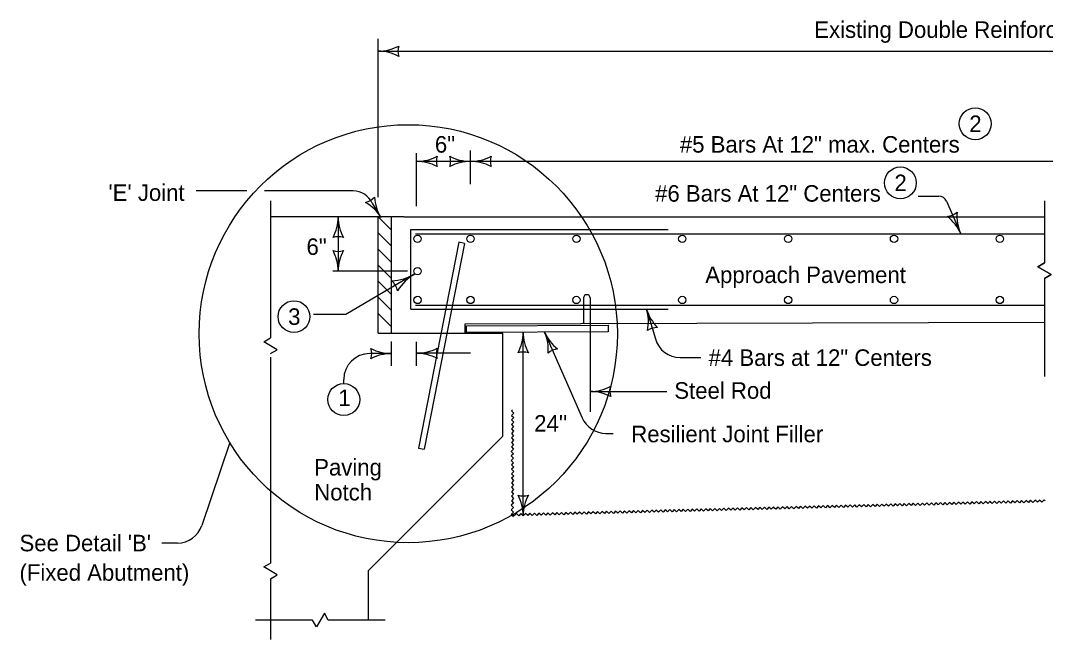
# Model space of a CAD drawing. Extents: x -2134860 to -2124557, y -2139046 to -2137324.
# Drawn here: x -2134860 to -2133869, y -2137923 to -2137324 of the extents above; entities that cross this region are included whole.
import ezdxf

# ---------------------------------------------------------------- set-up
doc = ezdxf.new("R2010")
doc.units = 0
for name, color, linetype in [('BridgeSuperStructureExisting', 7, 'Continuous'), ('dsnCellElements', 7, 'Continuous'), ('dsnStdLabel', 7, 'Continuous'), ('dsnTextFinalPlan', 7, 'Continuous')]:
    doc.layers.add(name, color=color, linetype=linetype)

msp = doc.modelspace()

# ---------------------------------------------------------------- linework, layer by layer
at = {"layer": 'BridgeSuperStructureExisting'}
for p, q in [((-2134618.16, -2137498.29), (-2134618.16, -2137537.43)), ((-2134519.9, -2137500.82), (-2134511.57, -2137514.44)), ((-2133870.3, -2137498.29), (-2133870.3, -2137558.37)), ((-2134489.26, -2137513.92), (-2134618.16, -2137513.92)), ((-2134514.26, -2137626.46), (-2134514.26, -2137513.92)), ((-2134501.39, -2137526.79), (-2134514.26, -2137513.92)), ((-2134489.26, -2137513.92), (-2133870.3, -2137513.92)), ((-2134482.68, -2137526.02), (-2134233.83, -2137526.02)), ((-2134482.68, -2137603.18), (-2134482.68, -2137526.02)), ((-2134501.39, -2137542.35), (-2134514.26, -2137529.48)), ((-2134478.05, -2137530.22), (-2133870.3, -2137530.22)), ((-2134618.16, -2137537.43), (-2134618.16, -2137631.03)), ((-2134501.39, -2137557.91), (-2134514.26, -2137545.04)), ((-2134501.39, -2137573.46), (-2134514.26, -2137560.59)), ((-2134501.39, -2137589.02), (-2134514.26, -2137576.15)), ((-2133870.3, -2137573.53), (-2133870.3, -2137668.14)), ((-2134501.39, -2137604.58), (-2134514.26, -2137591.71)), ((-2134482.68, -2137603.18), (-2134233.83, -2137603.18)), ((-2134478.05, -2137599.18), (-2133870.3, -2137599.18)), ((-2134501.39, -2137620.13), (-2134514.26, -2137607.26)), ((-2133870.3, -2137616.23), (-2134430.47, -2137617.72)), ((-2134428.74, -2137619.18), (-2134291.82, -2137618.68)), ((-2134428.72, -2137625.66), (-2134428.74, -2137619.18)), ((-2134291.8, -2137625.16), (-2134428.72, -2137625.66)), ((-2134291.82, -2137618.68), (-2134291.8, -2137625.16)), ((-2134514.26, -2137626.46), (-2134393.54, -2137626.46)), ((-2134393.53, -2137726.07), (-2134393.53, -2137626.46)), ((-2134618.16, -2137649.56), (-2134618.16, -2137848.65)), ((-2134523.37, -2137855.9), (-2134393.53, -2137726.07)), ((-2134618.16, -2137863.81), (-2134618.16, -2137922.62)), ((-2134523.37, -2137903.76), (-2134523.37, -2137855.9)), ((-2134577.54, -2137903.76), (-2134632.6, -2137903.76)), ((-2134507.32, -2137903.76), (-2134562.38, -2137903.76))]:
    msp.add_line(p, q, dxfattribs=at)
for points in [[(-2133870.3, -2137573.53), (-2133863.73, -2137569.74), (-2133876.86, -2137562.15), (-2133870.3, -2137558.37)], [(-2134618.15, -2137646.19), (-2134611.59, -2137642.41), (-2134624.72, -2137634.82), (-2134618.15, -2137631.04)], [(-2134618.15, -2137863.82), (-2134611.59, -2137860.03), (-2134624.72, -2137852.44), (-2134618.15, -2137848.66)], [(-2134562.37, -2137903.76), (-2134566.16, -2137897.2), (-2134573.75, -2137910.33), (-2134577.54, -2137903.76)]]:
    msp.add_lwpolyline(points, dxfattribs=at)
for centre, radius in [((-2133937.23, -2137423.93), 15.36), ((-2134009.56, -2137481.05), 15.36), ((-2134476.05, -2137535.22), 3.55), ((-2134424.9, -2137535.22), 3.55), ((-2134322.6, -2137535.22), 3.55), ((-2134220.29, -2137535.22), 3.55), ((-2134117.99, -2137535.22), 3.55), ((-2134015.68, -2137535.22), 3.55), ((-2133913.38, -2137535.22), 3.55), ((-2134595.54, -2137610.4), 15.36), ((-2134476.05, -2137594.28), 3.55), ((-2134424.9, -2137594.28), 3.55), ((-2134322.6, -2137594.28), 3.55), ((-2134220.29, -2137594.28), 3.55), ((-2134117.99, -2137594.28), 3.55), ((-2134015.68, -2137594.28), 3.55), ((-2133913.38, -2137594.28), 3.55), ((-2134547.36, -2137690.56), 15.36)]:
    msp.add_circle(centre, radius, dxfattribs=at)
for centre, radius, start, end in [((-2133965.92, -2137496.71), 16.85, 275.90677, 311.37347), ((-2133991.22, -2137547.72), 43.63, 23.64012, 51.71261), ((-2133911.28, -2137512.73), 43.63, 175.56763, 203.64012), ((-2134503.18, -2137527.36), 48.39, 272.40408, 300.47657), ((-2134513.6, -2137589.64), 18.69, 12.74322, 48.20992), ((-2134454.1, -2137610.76), 48.39, 120.47657, 148.54906), ((-2134222.28, -2137624.99), 25, 196.32643, 270), ((-2134522.36, -2137671.15), 25, 90, 180), ((-2134294.12, -2137698.28), 25, 203.64012, 270), ((-2134373.99, -2137767.33), 16.42, 252.26665, 287.73335), ((-2134416.49, -2137802.97), 42.5, 360, 28.07249), ((-2134331.49, -2137802.97), 42.5, 151.92751, 180), ((-2134708.21, -2137804.34), 25, 270, 341.40579)]:
    msp.add_arc(centre, radius, start, end, dxfattribs=at)
at = {"layer": 'dsnCellElements'}
for centre, radius, start, end in [((-2134514.26, -2137311.22), 42.5, 270, 298.07249), ((-2134478.62, -2137353.72), 16.42, 162.26665, 197.73335), ((-2134514.26, -2137396.22), 42.5, 61.92751, 90), ((-2134477.12, -2137417.78), 42.5, 270, 298.07249), ((-2134441.49, -2137460.28), 16.42, 162.26665, 197.73335), ((-2134460.54, -2137460.28), 16.42, 342.26665, 17.73335), ((-2134424.9, -2137417.78), 42.5, 241.92751, 270), ((-2134424.9, -2137417.78), 42.5, 270, 298.07249), ((-2134389.27, -2137460.28), 16.42, 162.26665, 197.73335), ((-2134477.12, -2137502.78), 42.5, 61.92751, 90), ((-2134424.9, -2137502.78), 42.5, 90, 118.07249), ((-2134424.9, -2137502.78), 42.5, 61.92751, 90), ((-2134530.16, -2137484.04), 16.42, 283.71154, 319.17824), ((-2134475.31, -2137492.27), 42.5, 183.3724, 211.44489), ((-2134547.83, -2137536.62), 42.5, 31.44489, 59.51738), ((-2134595.26, -2137513.92), 42.5, 331.92751, 360), ((-2134510.26, -2137513.92), 42.5, 180, 208.07249), ((-2134552.76, -2137549.56), 16.42, 72.26665, 107.73335), ((-2134552.76, -2137530.95), 16.42, 252.26665, 287.73335), ((-2134595.26, -2137566.59), 42.5, 360, 28.07249), ((-2134510.26, -2137566.59), 42.5, 151.92751, 180), ((-2134213.93, -2137591.24), 42.5, 196.32643, 224.39892), ((-2134295.5, -2137615.13), 42.5, 348.25394, 16.32643), ((-2134416.49, -2137625.46), 42.5, 331.92751, 360), ((-2134331.49, -2137625.46), 42.5, 180, 208.07249), ((-2134314.38, -2137608.34), 42.5, 203.64012, 231.71261), ((-2134392.25, -2137642.43), 42.5, 355.56763, 23.64012), ((-2134244.7, -2137637.38), 16.42, 88.59307, 124.05978), ((-2134536.83, -2137646.15), 16.42, 342.26665, 17.73335), ((-2134501.19, -2137603.65), 42.5, 241.92751, 270), ((-2134477.12, -2137603.37), 42.5, 270, 298.07249), ((-2134477.12, -2137688.37), 42.5, 61.92751, 90), ((-2134441.49, -2137645.87), 16.42, 162.26665, 197.73335), ((-2134373.99, -2137661.1), 16.42, 72.26665, 107.73335), ((-2134339.03, -2137658.03), 16.42, 95.90677, 131.37347), ((-2134501.19, -2137688.65), 42.5, 90, 118.07249), ((-2134309.44, -2137640.24), 42.5, 270, 298.07249), ((-2134309.44, -2137725.24), 42.5, 61.92751, 90), ((-2134273.81, -2137682.74), 16.42, 162.26665, 197.73335)]:
    msp.add_arc(centre, radius, start, end, dxfattribs=at)
at = {"layer": 'dsnStdLabel'}
for p, q in [((-2134514.26, -2137460.6), (-2134514.26, -2137341.67)), ((-2134514.26, -2137353.72), (-2133142.62, -2137353.72)), ((-2134477.12, -2137503.61), (-2134477.12, -2137452.42)), ((-2134424.9, -2137482.26), (-2134424.9, -2137449.69)), ((-2134514.26, -2137494.97), (-2134514.26, -2137460.6)), ((-2134424.9, -2137460.28), (-2134477.12, -2137460.28)), ((-2133854.65, -2137460.28), (-2134424.9, -2137460.28)), ((-2134681.13, -2137488.71), (-2134690, -2137488.71)), ((-2134641.15, -2137488.71), (-2134681.13, -2137488.71)), ((-2134538.42, -2137488.71), (-2134623.84, -2137488.71)), ((-2133992.31, -2137493.87), (-2133972.45, -2137493.87)), ((-2133965.05, -2137498.71), (-2133951.25, -2137530.22)), ((-2134552.76, -2137513.92), (-2134552.76, -2137566.59)), ((-2134501.39, -2137626.46), (-2134501.39, -2137513.92)), ((-2134436.23, -2137538.53), (-2134475.25, -2137737.56)), ((-2134430.67, -2137539.62), (-2134469.7, -2137738.65)), ((-2134430.67, -2137539.62), (-2134436.23, -2137538.53)), ((-2134485.85, -2137566.59), (-2134557.96, -2137566.59)), ((-2133870.3, -2137558.37), (-2133876.86, -2137562.15)), ((-2133876.86, -2137562.15), (-2133863.73, -2137569.74)), ((-2134478.64, -2137569.06), (-2134545.54, -2137608.43)), ((-2133863.73, -2137569.74), (-2133870.3, -2137573.53)), ((-2134254.72, -2137603.18), (-2134246.27, -2137632.01)), ((-2134545.54, -2137608.43), (-2134576.73, -2137608.43)), ((-2134430.47, -2137617.72), (-2134430.47, -2137626.46)), ((-2134428.74, -2137619.18), (-2134291.82, -2137618.68)), ((-2134428.72, -2137625.66), (-2134428.74, -2137619.18)), ((-2134291.8, -2137625.16), (-2134428.72, -2137625.66)), ((-2134373.99, -2137802.97), (-2134373.99, -2137625.46)), ((-2134353.32, -2137625.39), (-2134317.02, -2137708.31)), ((-2134291.82, -2137618.68), (-2134291.8, -2137625.16)), ((-2134501.39, -2137657.87), (-2134501.39, -2137634.56)), ((-2134477.12, -2137658.02), (-2134477.12, -2137634.7)), ((-2134424.9, -2137645.87), (-2134477.12, -2137645.87)), ((-2134501.19, -2137646.15), (-2134522.36, -2137646.15)), ((-2134222.28, -2137649.99), (-2134202.5, -2137649.99)), ((-2134547.36, -2137675.2), (-2134547.36, -2137671.15)), ((-2134309.44, -2137682.74), (-2134235.11, -2137682.74)), ((-2134294.12, -2137723.28), (-2134286.92, -2137723.28)), ((-2134657.57, -2137732.22), (-2134684.51, -2137812.31)), ((-2134475.25, -2137737.56), (-2134469.7, -2137738.65)), ((-2134708.21, -2137829.34), (-2134723.21, -2137829.34))]:
    msp.add_line(p, q, dxfattribs=at)
for points in [[(-2134384.26, -2137700.47), (-2134385.35, -2137701.55), (-2134383.18, -2137703.74), (-2134385.37, -2137705.91), (-2134383.2, -2137708.1), (-2134385.38, -2137710.27), (-2134383.21, -2137712.46), (-2134385.4, -2137714.63), (-2134383.22, -2137716.82), (-2134385.41, -2137719), (-2134383.24, -2137721.18), (-2134385.42, -2137723.35), (-2134383.26, -2137725.54), (-2134385.44, -2137727.71), (-2134383.27, -2137729.9), (-2134385.46, -2137732.08), (-2134383.28, -2137734.26), (-2134385.47, -2137736.44), (-2134383.3, -2137738.62), (-2134385.48, -2137740.8), (-2134383.31, -2137742.98), (-2134385.5, -2137745.16), (-2134383.33, -2137747.35), (-2134385.51, -2137749.52), (-2134383.34, -2137751.7), (-2134384.44, -2137752.78)], [(-2134384.26, -2137752.53), (-2134385.35, -2137753.62), (-2134383.19, -2137755.81), (-2134385.37, -2137757.98), (-2134383.2, -2137760.17), (-2134385.38, -2137762.34), (-2134383.21, -2137764.53), (-2134385.4, -2137766.7), (-2134383.23, -2137768.89), (-2134385.41, -2137771.07), (-2134383.24, -2137773.25), (-2134385.42, -2137775.42), (-2134383.26, -2137777.61), (-2134385.44, -2137779.78), (-2134383.27, -2137781.97), (-2134385.46, -2137784.15), (-2134383.28, -2137786.33), (-2134385.47, -2137788.51), (-2134383.3, -2137790.69), (-2134385.49, -2137792.87), (-2134383.31, -2137795.05), (-2134385.5, -2137797.22), (-2134383.33, -2137799.41), (-2134385.51, -2137801.58), (-2134383.34, -2137803.77)], [(-2134131.04, -2137795.5), (-2134132.16, -2137794.45), (-2134134.29, -2137796.68), (-2134136.52, -2137794.56), (-2134138.64, -2137796.79), (-2134140.88, -2137794.67), (-2134143, -2137796.9), (-2134145.24, -2137794.78), (-2134147.36, -2137797.02), (-2134149.6, -2137794.9), (-2134151.72, -2137797.13), (-2134153.95, -2137795.01), (-2134156.08, -2137797.24), (-2134158.32, -2137795.12), (-2134160.44, -2137797.36), (-2134162.67, -2137795.24), (-2134164.8, -2137797.47), (-2134167.03, -2137795.35), (-2134169.16, -2137797.59), (-2134171.4, -2137795.47), (-2134173.51, -2137797.7), (-2134175.75, -2137795.58), (-2134177.87, -2137797.82), (-2134180.11, -2137795.69), (-2134182.23, -2137797.93), (-2134183.35, -2137796.87)], [(-2134078.74, -2137794.13), (-2134079.85, -2137793.08), (-2134081.98, -2137795.31), (-2134084.22, -2137793.19), (-2134086.34, -2137795.42), (-2134088.57, -2137793.31), (-2134090.7, -2137795.54), (-2134092.93, -2137793.42), (-2134095.06, -2137795.65), (-2134097.29, -2137793.53), (-2134099.41, -2137795.76), (-2134101.65, -2137793.64), (-2134103.77, -2137795.88), (-2134106.01, -2137793.76), (-2134108.13, -2137795.99), (-2134110.37, -2137793.87), (-2134112.49, -2137796.11), (-2134114.73, -2137793.98), (-2134116.85, -2137796.22), (-2134119.09, -2137794.1), (-2134121.21, -2137796.34), (-2134123.45, -2137794.22), (-2134125.57, -2137796.45), (-2134127.8, -2137794.33), (-2134129.92, -2137796.56), (-2134131.04, -2137795.5)], [(-2134026.43, -2137792.77), (-2134027.55, -2137791.71), (-2134029.67, -2137793.94), (-2134031.91, -2137791.83), (-2134034.03, -2137794.06), (-2134036.27, -2137791.94), (-2134038.39, -2137794.17), (-2134040.63, -2137792.05), (-2134042.75, -2137794.28), (-2134044.99, -2137792.17), (-2134047.11, -2137794.4), (-2134049.35, -2137792.28), (-2134051.46, -2137794.51), (-2134053.7, -2137792.39), (-2134055.82, -2137794.63), (-2134058.06, -2137792.5), (-2134060.18, -2137794.74), (-2134062.42, -2137792.62), (-2134064.55, -2137794.85), (-2134066.78, -2137792.73), (-2134068.9, -2137794.97), (-2134071.14, -2137792.85), (-2134073.26, -2137795.08), (-2134075.5, -2137792.96), (-2134077.62, -2137795.2), (-2134078.74, -2137794.13)], [(-2133974.12, -2137791.4), (-2133975.24, -2137790.35), (-2133977.36, -2137792.58), (-2133979.6, -2137790.46), (-2133981.72, -2137792.69), (-2133983.96, -2137790.57), (-2133986.09, -2137792.81), (-2133988.32, -2137790.69), (-2133990.44, -2137792.92), (-2133992.68, -2137790.8), (-2133994.8, -2137793.03), (-2133997.04, -2137790.91), (-2133999.16, -2137793.14), (-2134001.4, -2137791.03), (-2134003.52, -2137793.26), (-2134005.76, -2137791.14), (-2134007.87, -2137793.37), (-2134010.11, -2137791.25), (-2134012.24, -2137793.49), (-2134014.47, -2137791.37), (-2134016.6, -2137793.6), (-2134018.83, -2137791.48), (-2134020.96, -2137793.72), (-2134023.19, -2137791.6), (-2134025.31, -2137793.83), (-2134026.43, -2137792.77)], [(-2133921.81, -2137790.04), (-2133922.93, -2137788.98), (-2133925.06, -2137791.21), (-2133927.29, -2137789.09), (-2133929.42, -2137791.32), (-2133931.65, -2137789.21), (-2133933.78, -2137791.44), (-2133936.02, -2137789.32), (-2133938.14, -2137791.55), (-2133940.37, -2137789.43), (-2133942.5, -2137791.66), (-2133944.73, -2137789.55), (-2133946.85, -2137791.78), (-2133949.09, -2137789.66), (-2133951.21, -2137791.89), (-2133953.45, -2137789.77), (-2133955.57, -2137792), (-2133957.8, -2137789.89), (-2133959.93, -2137792.12), (-2133962.17, -2137790), (-2133964.29, -2137792.23), (-2133966.52, -2137790.12), (-2133968.65, -2137792.35), (-2133970.88, -2137790.23), (-2133973.01, -2137792.46), (-2133974.12, -2137791.4)], [(-2133869.51, -2137788.67), (-2133870.63, -2137787.61), (-2133872.75, -2137789.85), (-2133874.99, -2137787.73), (-2133877.11, -2137789.96), (-2133879.35, -2137787.84), (-2133881.47, -2137790.07), (-2133883.71, -2137787.95), (-2133885.83, -2137790.19), (-2133888.07, -2137788.07), (-2133890.19, -2137790.3), (-2133892.42, -2137788.18), (-2133894.55, -2137790.41), (-2133896.78, -2137788.29), (-2133898.91, -2137790.52), (-2133901.15, -2137788.41), (-2133903.26, -2137790.64), (-2133905.5, -2137788.52), (-2133907.62, -2137790.75), (-2133909.86, -2137788.64), (-2133911.99, -2137790.87), (-2133914.22, -2137788.75), (-2133916.34, -2137790.99), (-2133918.58, -2137788.87), (-2133920.7, -2137791.09), (-2133921.81, -2137790.04)], [(-2134340.26, -2137800.96), (-2134341.38, -2137799.91), (-2134343.51, -2137802.14), (-2134345.74, -2137800.02), (-2134347.87, -2137802.25), (-2134350.1, -2137800.14), (-2134352.22, -2137802.37), (-2134354.46, -2137800.25), (-2134356.58, -2137802.48), (-2134358.82, -2137800.36), (-2134360.95, -2137802.59), (-2134363.18, -2137800.47), (-2134365.3, -2137802.71), (-2134367.54, -2137800.59), (-2134369.66, -2137802.82), (-2134371.9, -2137800.7), (-2134374.02, -2137802.94), (-2134376.26, -2137800.82), (-2134378.38, -2137803.05), (-2134380.62, -2137800.93), (-2134382.74, -2137803.16), (-2134383.8, -2137802.15)], [(-2134287.96, -2137799.6), (-2134289.08, -2137798.54), (-2134291.2, -2137800.77), (-2134293.44, -2137798.66), (-2134295.56, -2137800.89), (-2134297.8, -2137798.77), (-2134299.92, -2137801), (-2134302.16, -2137798.88), (-2134304.28, -2137801.11), (-2134306.52, -2137799), (-2134308.64, -2137801.23), (-2134310.87, -2137799.11), (-2134312.99, -2137801.34), (-2134315.23, -2137799.22), (-2134317.36, -2137801.45), (-2134319.6, -2137799.33), (-2134321.71, -2137801.57), (-2134323.95, -2137799.45), (-2134326.07, -2137801.68), (-2134328.31, -2137799.56), (-2134330.44, -2137801.8), (-2134332.67, -2137799.68), (-2134334.79, -2137801.91), (-2134337.03, -2137799.79), (-2134339.15, -2137802.03), (-2134340.26, -2137800.96)], [(-2134235.66, -2137798.23), (-2134236.77, -2137797.18), (-2134238.89, -2137799.41), (-2134241.13, -2137797.29), (-2134243.26, -2137799.52), (-2134245.5, -2137797.4), (-2134247.61, -2137799.64), (-2134249.85, -2137797.52), (-2134251.97, -2137799.75), (-2134254.21, -2137797.63), (-2134256.34, -2137799.86), (-2134258.57, -2137797.74), (-2134260.69, -2137799.97), (-2134262.92, -2137797.86), (-2134265.05, -2137800.09), (-2134267.29, -2137797.97), (-2134269.41, -2137800.2), (-2134271.65, -2137798.08), (-2134273.77, -2137800.32), (-2134276, -2137798.2), (-2134278.13, -2137800.43), (-2134280.36, -2137798.31), (-2134282.49, -2137800.55), (-2134284.72, -2137798.43), (-2134286.84, -2137800.66), (-2134287.96, -2137799.6)], [(-2134183.35, -2137796.87), (-2134184.47, -2137795.81), (-2134186.59, -2137798.04), (-2134188.82, -2137795.92), (-2134190.95, -2137798.16), (-2134193.19, -2137796.04), (-2134195.31, -2137798.27), (-2134197.55, -2137796.15), (-2134199.67, -2137798.38), (-2134201.9, -2137796.26), (-2134204.03, -2137798.49), (-2134206.26, -2137796.38), (-2134208.39, -2137798.61), (-2134210.62, -2137796.49), (-2134212.74, -2137798.72), (-2134214.98, -2137796.6), (-2134217.1, -2137798.84), (-2134219.34, -2137796.72), (-2134221.46, -2137798.95), (-2134223.7, -2137796.83), (-2134225.82, -2137799.07), (-2134228.05, -2137796.95), (-2134230.18, -2137799.18), (-2134232.42, -2137797.06), (-2134234.53, -2137799.3), (-2134235.66, -2137798.23)]]:
    msp.add_lwpolyline(points, dxfattribs=at)
for centre, radius in [((-2134485.1, -2137626.91), 202.08), ((-2134476.05, -2137566.42), 3.55)]:
    msp.add_circle(centre, radius, dxfattribs=at)
for centre, radius in [((-2134538.42, -2137508.92), 20.21), ((-2133972.45, -2137501.95), 8.08)]:
    msp.add_arc(centre, radius, 23.64012, 90, dxfattribs=at)
at = {"layer": 'dsnTextFinalPlan'}
for p, q in [((-2134315.74, -2137592.34), (-2134315.74, -2137616.49)), ((-2134309.44, -2137592.34), (-2134309.44, -2137702.56))]:
    msp.add_line(p, q, dxfattribs=at)
msp.add_arc((-2134312.59, -2137592.34), 3.15, 0, 180, dxfattribs=at)

# ---------------------------------------------------------------- texts
at = {"layer": 'dsnStdLabel'}
for s, p in [('Existing Double Reinforced Section (20\'-0" min.)', (-2134092.73, -2137340.88)), ('2', (-2133942.96, -2137431.93)), ('6"', (-2134459.34, -2137451.83)), ('#5 Bars At 12" max. Centers', (-2134222.61, -2137451.82)), ('2', (-2134015.29, -2137489.05)), ("'E' Joint", (-2134774.78, -2137498.48)), ('#6 Bars At 12" Centers', (-2134246.51, -2137499.24)), ('6"', (-2134583.41, -2137550.72)), ('Approach Pavement', (-2134198.08, -2137577.95)), ('3', (-2134601.13, -2137618.4)), ('#4 Bars at 12" Centers', (-2134194.84, -2137658.05)), ('Steel Rod', (-2134228, -2137689.82)), ('1', (-2134552.61, -2137696.95)), ("24''", (-2134363.37, -2137721.6)), ('Resilient Joint Filler', (-2134269.57, -2137731.9)), ('Paving', (-2134575.95, -2137764.05)), ('Notch', (-2134575.95, -2137788.14)), ("See Detail 'B'", (-2134860.73, -2137837.34)), ('(Fixed Abutment)', (-2134860.73, -2137865.85))]:
    msp.add_text(s, height=16, dxfattribs=at).set_placement(p)

doc.saveas('drawing.dxf')
